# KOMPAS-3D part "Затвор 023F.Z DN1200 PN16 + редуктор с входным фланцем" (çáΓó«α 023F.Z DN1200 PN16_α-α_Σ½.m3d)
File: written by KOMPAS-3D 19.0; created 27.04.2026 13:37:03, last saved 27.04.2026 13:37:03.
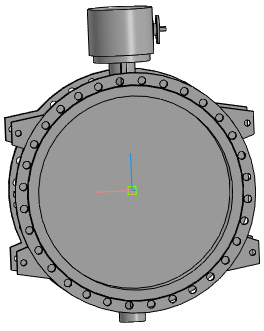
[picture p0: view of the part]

Document properties: Полное имя файла: ..\..\Затвор 023F.Z DN200-DN1600_редуктор с входным фланцем\Затвор 023F.Z DN1200 PN16 + редуктор с входным фланцем.a3d

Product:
- Part/product: Затвор 023F.Z DN1200 PN16 + редуктор с входным фланцем
    Масса: 2202.09

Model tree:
1. Операция без истории:1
